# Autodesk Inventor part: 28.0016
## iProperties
Created: 2013-02
Part Number: 28.0016
Material: Aluminum-6061
Document SubType Name: Modeling
Designer: Administrator
Density: 2.71 g/cm^3
Mass: 524.753 g
Surface Area: 1478.16 cm^2
Volume: 193.636 cm^3
Description: Linear Rail LR 6
Author: Administrator
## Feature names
1. Extrusion1
2. Hole1
3. Rectangular Pattern1
